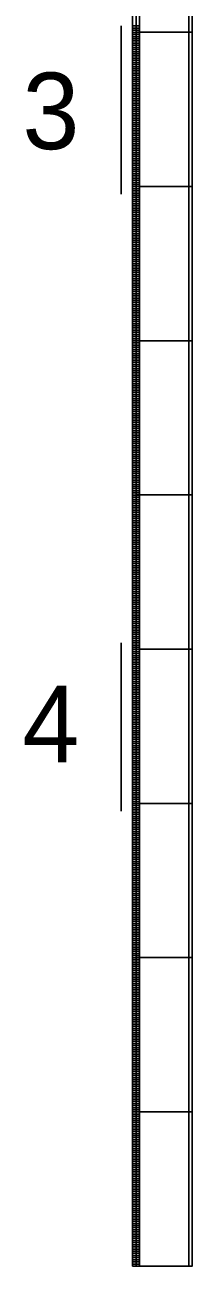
# Model space of a CAD drawing. Extents: x -13 to 29, y -301 to 22.
# Drawn here: x -12.6 to 9.3, y -301.4 to -139.2 of the extents above; entities that cross this region are included whole.
import ezdxf

# ---------------------------------------------------------------- set-up
doc = ezdxf.new("R2010")
doc.units = 0
doc.layers.add('SC_Scratch1', color=7, linetype='Continuous')
doc.layers.add('SH_Text', color=7, linetype='Continuous')

msp = doc.modelspace()

# ---------------------------------------------------------------- linework, layer by layer
at = {"layer": 'SH_Text'}
for p, q in [((1.5, -140.14), (1.5, -119.98)), ((2.4, -140.14), (2.4, -119.98)), ((8.84, -140.14), (8.84, -119.98)), ((0, -139.28), (0, -161.28)), ((1.5, -139.3), (2.4, -139.3)), ((1.5, -139.58), (2.4, -139.58)), ((1.5, -139.86), (2.4, -139.86)), ((1.5, -140.14), (2.4, -140.14)), ((1.5, -140.14), (2.4, -140.14)), ((1.5, -160.3), (1.5, -140.14)), ((1.5, -140.42), (2.4, -140.42)), ((1.5, -140.7), (2.4, -140.7)), ((1.5, -140.98), (2.4, -140.98)), ((2.4, -160.3), (2.4, -140.14)), ((8.84, -160.3), (8.84, -140.14)), ((1.5, -141.26), (2.4, -141.26)), ((1.5, -141.54), (2.4, -141.54)), ((1.5, -141.82), (2.4, -141.82)), ((1.5, -142.1), (2.4, -142.1)), ((1.5, -142.38), (2.4, -142.38)), ((1.5, -142.66), (2.4, -142.66)), ((1.5, -142.94), (2.4, -142.94)), ((1.5, -143.22), (2.4, -143.22)), ((1.5, -143.5), (2.4, -143.5)), ((1.5, -143.78), (2.4, -143.78)), ((1.5, -144.06), (2.4, -144.06)), ((1.5, -144.34), (2.4, -144.34)), ((1.5, -144.62), (2.4, -144.62)), ((1.5, -144.9), (2.4, -144.9)), ((1.5, -145.18), (2.4, -145.18)), ((1.5, -145.46), (2.4, -145.46)), ((1.5, -145.74), (2.4, -145.74)), ((1.5, -146.02), (2.4, -146.02)), ((1.5, -146.3), (2.4, -146.3)), ((1.5, -146.58), (2.4, -146.58)), ((1.5, -146.86), (2.4, -146.86)), ((1.5, -147.14), (2.4, -147.14)), ((1.5, -147.42), (2.4, -147.42)), ((1.5, -147.7), (2.4, -147.7)), ((1.5, -147.98), (2.4, -147.98)), ((1.5, -148.26), (2.4, -148.26)), ((1.5, -148.54), (2.4, -148.54)), ((1.5, -148.82), (2.4, -148.82)), ((1.5, -149.1), (2.4, -149.1)), ((1.5, -149.38), (2.4, -149.38)), ((1.5, -149.66), (2.4, -149.66)), ((1.5, -149.94), (2.4, -149.94)), ((1.5, -150.22), (2.4, -150.22)), ((1.5, -150.5), (2.4, -150.5)), ((1.5, -150.78), (2.4, -150.78)), ((1.5, -151.06), (2.4, -151.06)), ((1.5, -151.34), (2.4, -151.34)), ((1.5, -151.62), (2.4, -151.62)), ((1.5, -151.9), (2.4, -151.9)), ((1.5, -152.18), (2.4, -152.18)), ((1.5, -152.46), (2.4, -152.46)), ((1.5, -152.74), (2.4, -152.74)), ((1.5, -153.02), (2.4, -153.02)), ((1.5, -153.3), (2.4, -153.3)), ((1.5, -153.58), (2.4, -153.58)), ((1.5, -153.86), (2.4, -153.86)), ((1.5, -154.14), (2.4, -154.14)), ((1.5, -154.42), (2.4, -154.42)), ((1.5, -154.7), (2.4, -154.7)), ((1.5, -154.98), (2.4, -154.98)), ((1.5, -155.26), (2.4, -155.26)), ((1.5, -155.54), (2.4, -155.54)), ((1.5, -155.82), (2.4, -155.82)), ((1.5, -156.1), (2.4, -156.1)), ((1.5, -156.38), (2.4, -156.38)), ((1.5, -156.66), (2.4, -156.66)), ((1.5, -156.94), (2.4, -156.94)), ((1.5, -157.22), (2.4, -157.22)), ((1.5, -157.5), (2.4, -157.5)), ((1.5, -157.78), (2.4, -157.78)), ((1.5, -158.06), (2.4, -158.06)), ((1.5, -158.34), (2.4, -158.34)), ((1.5, -158.62), (2.4, -158.62)), ((1.5, -158.9), (2.4, -158.9)), ((1.5, -159.18), (2.4, -159.18)), ((1.5, -159.46), (2.4, -159.46)), ((1.5, -159.74), (2.4, -159.74)), ((1.5, -160.02), (2.4, -160.02)), ((1.5, -160.3), (2.4, -160.3)), ((1.5, -160.3), (2.4, -160.3)), ((1.5, -180.46), (1.5, -160.3)), ((1.5, -160.58), (2.4, -160.58)), ((2.4, -180.46), (2.4, -160.3)), ((8.84, -180.46), (8.84, -160.3)), ((1.5, -160.86), (2.4, -160.86)), ((1.5, -161.14), (2.4, -161.14)), ((1.5, -161.42), (2.4, -161.42)), ((1.5, -161.7), (2.4, -161.7)), ((1.5, -161.98), (2.4, -161.98)), ((1.5, -162.26), (2.4, -162.26)), ((1.5, -162.54), (2.4, -162.54)), ((1.5, -162.82), (2.4, -162.82)), ((1.5, -163.1), (2.4, -163.1)), ((1.5, -163.38), (2.4, -163.38)), ((1.5, -163.66), (2.4, -163.66)), ((1.5, -163.94), (2.4, -163.94)), ((1.5, -164.22), (2.4, -164.22)), ((1.5, -164.5), (2.4, -164.5)), ((1.5, -164.78), (2.4, -164.78)), ((1.5, -165.06), (2.4, -165.06)), ((1.5, -165.34), (2.4, -165.34)), ((1.5, -165.62), (2.4, -165.62)), ((1.5, -165.9), (2.4, -165.9)), ((1.5, -166.18), (2.4, -166.18)), ((1.5, -166.46), (2.4, -166.46)), ((1.5, -166.74), (2.4, -166.74)), ((1.5, -167.02), (2.4, -167.02)), ((1.5, -167.3), (2.4, -167.3)), ((1.5, -167.58), (2.4, -167.58)), ((1.5, -167.86), (2.4, -167.86)), ((1.5, -168.14), (2.4, -168.14)), ((1.5, -168.42), (2.4, -168.42)), ((1.5, -168.7), (2.4, -168.7)), ((1.5, -168.98), (2.4, -168.98)), ((1.5, -169.26), (2.4, -169.26)), ((1.5, -169.54), (2.4, -169.54)), ((1.5, -169.82), (2.4, -169.82)), ((1.5, -170.1), (2.4, -170.1)), ((1.5, -170.38), (2.4, -170.38)), ((1.5, -170.66), (2.4, -170.66)), ((1.5, -170.94), (2.4, -170.94)), ((1.5, -171.22), (2.4, -171.22)), ((1.5, -171.5), (2.4, -171.5)), ((1.5, -171.78), (2.4, -171.78)), ((1.5, -172.06), (2.4, -172.06)), ((1.5, -172.34), (2.4, -172.34)), ((1.5, -172.62), (2.4, -172.62)), ((1.5, -172.9), (2.4, -172.9)), ((1.5, -173.18), (2.4, -173.18)), ((1.5, -173.46), (2.4, -173.46)), ((1.5, -173.74), (2.4, -173.74)), ((1.5, -174.02), (2.4, -174.02)), ((1.5, -174.3), (2.4, -174.3)), ((1.5, -174.58), (2.4, -174.58)), ((1.5, -174.86), (2.4, -174.86)), ((1.5, -175.14), (2.4, -175.14)), ((1.5, -175.42), (2.4, -175.42)), ((1.5, -175.7), (2.4, -175.7)), ((1.5, -175.98), (2.4, -175.98)), ((1.5, -176.26), (2.4, -176.26)), ((1.5, -176.54), (2.4, -176.54)), ((1.5, -176.82), (2.4, -176.82)), ((1.5, -177.1), (2.4, -177.1)), ((1.5, -177.38), (2.4, -177.38)), ((1.5, -177.66), (2.4, -177.66)), ((1.5, -177.94), (2.4, -177.94)), ((1.5, -178.22), (2.4, -178.22)), ((1.5, -178.5), (2.4, -178.5)), ((1.5, -178.78), (2.4, -178.78)), ((1.5, -179.06), (2.4, -179.06)), ((1.5, -179.34), (2.4, -179.34)), ((1.5, -179.62), (2.4, -179.62)), ((1.5, -179.9), (2.4, -179.9)), ((1.5, -180.18), (2.4, -180.18)), ((1.5, -180.46), (2.4, -180.46)), ((1.5, -180.46), (2.4, -180.46)), ((1.5, -200.62), (1.5, -180.46)), ((1.5, -180.74), (2.4, -180.74)), ((1.5, -181.02), (2.4, -181.02)), ((1.5, -181.3), (2.4, -181.3)), ((1.5, -181.58), (2.4, -181.58)), ((2.4, -200.62), (2.4, -180.46)), ((8.84, -200.62), (8.84, -180.46)), ((1.5, -181.86), (2.4, -181.86)), ((1.5, -182.14), (2.4, -182.14)), ((1.5, -182.42), (2.4, -182.42)), ((1.5, -182.7), (2.4, -182.7)), ((1.5, -182.98), (2.4, -182.98)), ((1.5, -183.26), (2.4, -183.26)), ((1.5, -183.54), (2.4, -183.54)), ((1.5, -183.82), (2.4, -183.82)), ((1.5, -184.1), (2.4, -184.1)), ((1.5, -184.38), (2.4, -184.38)), ((1.5, -184.66), (2.4, -184.66)), ((1.5, -184.94), (2.4, -184.94)), ((1.5, -185.22), (2.4, -185.22)), ((1.5, -185.5), (2.4, -185.5)), ((1.5, -185.78), (2.4, -185.78)), ((1.5, -186.06), (2.4, -186.06)), ((1.5, -186.34), (2.4, -186.34)), ((1.5, -186.62), (2.4, -186.62)), ((1.5, -186.9), (2.4, -186.9)), ((1.5, -187.18), (2.4, -187.18)), ((1.5, -187.46), (2.4, -187.46)), ((1.5, -187.74), (2.4, -187.74)), ((1.5, -188.02), (2.4, -188.02)), ((1.5, -188.3), (2.4, -188.3)), ((1.5, -188.58), (2.4, -188.58)), ((1.5, -188.86), (2.4, -188.86)), ((1.5, -189.14), (2.4, -189.14)), ((1.5, -189.42), (2.4, -189.42)), ((1.5, -189.7), (2.4, -189.7)), ((1.5, -189.98), (2.4, -189.98)), ((1.5, -190.26), (2.4, -190.26)), ((1.5, -190.54), (2.4, -190.54)), ((1.5, -190.82), (2.4, -190.82)), ((1.5, -191.1), (2.4, -191.1)), ((1.5, -191.38), (2.4, -191.38)), ((1.5, -191.66), (2.4, -191.66)), ((1.5, -191.94), (2.4, -191.94)), ((1.5, -192.22), (2.4, -192.22)), ((1.5, -192.5), (2.4, -192.5)), ((1.5, -192.78), (2.4, -192.78)), ((1.5, -193.06), (2.4, -193.06)), ((1.5, -193.34), (2.4, -193.34)), ((1.5, -193.62), (2.4, -193.62)), ((1.5, -193.9), (2.4, -193.9)), ((1.5, -194.18), (2.4, -194.18)), ((1.5, -194.46), (2.4, -194.46)), ((1.5, -194.74), (2.4, -194.74)), ((1.5, -195.02), (2.4, -195.02)), ((1.5, -195.3), (2.4, -195.3)), ((1.5, -195.58), (2.4, -195.58)), ((1.5, -195.86), (2.4, -195.86)), ((1.5, -196.14), (2.4, -196.14)), ((1.5, -196.42), (2.4, -196.42)), ((1.5, -196.7), (2.4, -196.7)), ((1.5, -196.98), (2.4, -196.98)), ((1.5, -197.26), (2.4, -197.26)), ((1.5, -197.54), (2.4, -197.54)), ((1.5, -197.82), (2.4, -197.82)), ((1.5, -198.1), (2.4, -198.1)), ((1.5, -198.38), (2.4, -198.38)), ((1.5, -198.66), (2.4, -198.66)), ((1.5, -198.94), (2.4, -198.94)), ((1.5, -199.22), (2.4, -199.22)), ((1.5, -199.5), (2.4, -199.5)), ((1.5, -199.78), (2.4, -199.78)), ((1.5, -200.06), (2.4, -200.06)), ((1.5, -200.34), (2.4, -200.34)), ((1.5, -200.62), (2.4, -200.62)), ((1.5, -200.62), (2.4, -200.62)), ((1.5, -220.78), (1.5, -200.62)), ((1.5, -200.9), (2.4, -200.9)), ((1.5, -201.18), (2.4, -201.18)), ((2.4, -220.78), (2.4, -200.62)), ((8.84, -220.78), (8.84, -200.62)), ((1.5, -201.46), (2.4, -201.46)), ((1.5, -201.74), (2.4, -201.74)), ((1.5, -202.02), (2.4, -202.02)), ((1.5, -202.3), (2.4, -202.3)), ((1.5, -202.58), (2.4, -202.58)), ((1.5, -202.86), (2.4, -202.86)), ((1.5, -203.14), (2.4, -203.14)), ((1.5, -203.42), (2.4, -203.42)), ((1.5, -203.7), (2.4, -203.7)), ((1.5, -203.98), (2.4, -203.98)), ((1.5, -204.26), (2.4, -204.26)), ((1.5, -204.54), (2.4, -204.54)), ((1.5, -204.82), (2.4, -204.82)), ((1.5, -205.1), (2.4, -205.1)), ((1.5, -205.38), (2.4, -205.38)), ((1.5, -205.66), (2.4, -205.66)), ((1.5, -205.94), (2.4, -205.94)), ((1.5, -206.22), (2.4, -206.22)), ((1.5, -206.5), (2.4, -206.5)), ((1.5, -206.78), (2.4, -206.78)), ((1.5, -207.06), (2.4, -207.06)), ((1.5, -207.34), (2.4, -207.34)), ((1.5, -207.62), (2.4, -207.62)), ((1.5, -207.9), (2.4, -207.9)), ((1.5, -208.18), (2.4, -208.18)), ((1.5, -208.46), (2.4, -208.46)), ((1.5, -208.74), (2.4, -208.74)), ((1.5, -209.02), (2.4, -209.02)), ((1.5, -209.3), (2.4, -209.3)), ((1.5, -209.58), (2.4, -209.58)), ((1.5, -209.86), (2.4, -209.86)), ((1.5, -210.14), (2.4, -210.14)), ((1.5, -210.42), (2.4, -210.42)), ((1.5, -210.7), (2.4, -210.7)), ((1.5, -210.98), (2.4, -210.98)), ((1.5, -211.26), (2.4, -211.26)), ((1.5, -211.54), (2.4, -211.54)), ((1.5, -211.82), (2.4, -211.82)), ((1.5, -212.1), (2.4, -212.1)), ((1.5, -212.38), (2.4, -212.38)), ((1.5, -212.66), (2.4, -212.66)), ((1.5, -212.94), (2.4, -212.94)), ((1.5, -213.22), (2.4, -213.22)), ((1.5, -213.5), (2.4, -213.5)), ((1.5, -213.78), (2.4, -213.78)), ((1.5, -214.06), (2.4, -214.06)), ((1.5, -214.34), (2.4, -214.34)), ((1.5, -214.62), (2.4, -214.62)), ((1.5, -214.9), (2.4, -214.9)), ((1.5, -215.18), (2.4, -215.18)), ((1.5, -215.46), (2.4, -215.46)), ((1.5, -215.74), (2.4, -215.74)), ((1.5, -216.02), (2.4, -216.02)), ((1.5, -216.3), (2.4, -216.3)), ((1.5, -216.58), (2.4, -216.58)), ((1.5, -216.86), (2.4, -216.86)), ((1.5, -217.14), (2.4, -217.14)), ((1.5, -217.42), (2.4, -217.42)), ((1.5, -217.7), (2.4, -217.7)), ((1.5, -217.98), (2.4, -217.98)), ((1.5, -218.26), (2.4, -218.26)), ((1.5, -218.54), (2.4, -218.54)), ((1.5, -218.82), (2.4, -218.82)), ((0, -219.92), (0, -241.92)), ((1.5, -219.1), (2.4, -219.1)), ((1.5, -219.38), (2.4, -219.38)), ((1.5, -219.66), (2.4, -219.66)), ((1.5, -219.94), (2.4, -219.94)), ((1.5, -220.22), (2.4, -220.22)), ((1.5, -220.5), (2.4, -220.5)), ((1.5, -220.78), (2.4, -220.78)), ((1.5, -220.78), (2.4, -220.78)), ((1.5, -240.94), (1.5, -220.78)), ((1.5, -221.06), (2.4, -221.06)), ((1.5, -221.34), (2.4, -221.34)), ((1.5, -221.62), (2.4, -221.62)), ((1.5, -221.9), (2.4, -221.9)), ((1.5, -222.18), (2.4, -222.18)), ((2.4, -240.94), (2.4, -220.78)), ((8.84, -240.94), (8.84, -220.78)), ((1.5, -222.46), (2.4, -222.46)), ((1.5, -222.74), (2.4, -222.74)), ((1.5, -223.02), (2.4, -223.02)), ((1.5, -223.3), (2.4, -223.3)), ((1.5, -223.58), (2.4, -223.58)), ((1.5, -223.86), (2.4, -223.86)), ((1.5, -224.14), (2.4, -224.14)), ((1.5, -224.42), (2.4, -224.42)), ((1.5, -224.7), (2.4, -224.7)), ((1.5, -224.98), (2.4, -224.98)), ((1.5, -225.26), (2.4, -225.26)), ((1.5, -225.54), (2.4, -225.54)), ((1.5, -225.82), (2.4, -225.82)), ((1.5, -226.1), (2.4, -226.1)), ((1.5, -226.38), (2.4, -226.38)), ((1.5, -226.66), (2.4, -226.66)), ((1.5, -226.94), (2.4, -226.94)), ((1.5, -227.22), (2.4, -227.22)), ((1.5, -227.5), (2.4, -227.5)), ((1.5, -227.78), (2.4, -227.78)), ((1.5, -228.06), (2.4, -228.06)), ((1.5, -228.34), (2.4, -228.34)), ((1.5, -228.62), (2.4, -228.62)), ((1.5, -228.9), (2.4, -228.9)), ((1.5, -229.18), (2.4, -229.18)), ((1.5, -229.46), (2.4, -229.46)), ((1.5, -229.74), (2.4, -229.74)), ((1.5, -230.02), (2.4, -230.02)), ((1.5, -230.3), (2.4, -230.3)), ((1.5, -230.58), (2.4, -230.58)), ((1.5, -230.86), (2.4, -230.86)), ((1.5, -231.14), (2.4, -231.14)), ((1.5, -231.42), (2.4, -231.42)), ((1.5, -231.7), (2.4, -231.7)), ((1.5, -231.98), (2.4, -231.98)), ((1.5, -232.26), (2.4, -232.26)), ((1.5, -232.54), (2.4, -232.54)), ((1.5, -232.82), (2.4, -232.82)), ((1.5, -233.1), (2.4, -233.1)), ((1.5, -233.38), (2.4, -233.38)), ((1.5, -233.66), (2.4, -233.66)), ((1.5, -233.94), (2.4, -233.94)), ((1.5, -234.22), (2.4, -234.22)), ((1.5, -234.5), (2.4, -234.5)), ((1.5, -234.78), (2.4, -234.78)), ((1.5, -235.06), (2.4, -235.06)), ((1.5, -235.34), (2.4, -235.34)), ((1.5, -235.62), (2.4, -235.62)), ((1.5, -235.9), (2.4, -235.9)), ((1.5, -236.18), (2.4, -236.18)), ((1.5, -236.46), (2.4, -236.46)), ((1.5, -236.74), (2.4, -236.74)), ((1.5, -237.02), (2.4, -237.02)), ((1.5, -237.3), (2.4, -237.3)), ((1.5, -237.58), (2.4, -237.58)), ((1.5, -237.86), (2.4, -237.86)), ((1.5, -238.14), (2.4, -238.14)), ((1.5, -238.42), (2.4, -238.42)), ((1.5, -238.7), (2.4, -238.7)), ((1.5, -238.98), (2.4, -238.98)), ((1.5, -239.26), (2.4, -239.26)), ((1.5, -239.54), (2.4, -239.54)), ((1.5, -239.82), (2.4, -239.82)), ((1.5, -240.1), (2.4, -240.1)), ((1.5, -240.38), (2.4, -240.38)), ((1.5, -240.66), (2.4, -240.66)), ((1.5, -240.94), (2.4, -240.94)), ((1.5, -240.94), (2.4, -240.94)), ((1.5, -261.1), (1.5, -240.94)), ((1.5, -241.22), (2.4, -241.22)), ((1.5, -241.5), (2.4, -241.5)), ((1.5, -241.78), (2.4, -241.78)), ((2.4, -261.1), (2.4, -240.94)), ((8.84, -261.1), (8.84, -240.94)), ((1.5, -242.06), (2.4, -242.06)), ((1.5, -242.34), (2.4, -242.34)), ((1.5, -242.62), (2.4, -242.62)), ((1.5, -242.9), (2.4, -242.9)), ((1.5, -243.18), (2.4, -243.18)), ((1.5, -243.46), (2.4, -243.46)), ((1.5, -243.74), (2.4, -243.74)), ((1.5, -244.02), (2.4, -244.02)), ((1.5, -244.3), (2.4, -244.3)), ((1.5, -244.58), (2.4, -244.58)), ((1.5, -244.86), (2.4, -244.86)), ((1.5, -245.14), (2.4, -245.14)), ((1.5, -245.42), (2.4, -245.42)), ((1.5, -245.7), (2.4, -245.7)), ((1.5, -245.98), (2.4, -245.98)), ((1.5, -246.26), (2.4, -246.26)), ((1.5, -246.54), (2.4, -246.54)), ((1.5, -246.82), (2.4, -246.82)), ((1.5, -247.1), (2.4, -247.1)), ((1.5, -247.38), (2.4, -247.38)), ((1.5, -247.66), (2.4, -247.66)), ((1.5, -247.94), (2.4, -247.94)), ((1.5, -248.22), (2.4, -248.22)), ((1.5, -248.5), (2.4, -248.5)), ((1.5, -248.78), (2.4, -248.78)), ((1.5, -249.06), (2.4, -249.06)), ((1.5, -249.34), (2.4, -249.34)), ((1.5, -249.62), (2.4, -249.62)), ((1.5, -249.9), (2.4, -249.9)), ((1.5, -250.18), (2.4, -250.18)), ((1.5, -250.46), (2.4, -250.46)), ((1.5, -250.74), (2.4, -250.74)), ((1.5, -251.02), (2.4, -251.02)), ((1.5, -251.3), (2.4, -251.3)), ((1.5, -251.58), (2.4, -251.58)), ((1.5, -251.86), (2.4, -251.86)), ((1.5, -252.14), (2.4, -252.14)), ((1.5, -252.42), (2.4, -252.42)), ((1.5, -252.7), (2.4, -252.7)), ((1.5, -252.98), (2.4, -252.98)), ((1.5, -253.26), (2.4, -253.26)), ((1.5, -253.54), (2.4, -253.54)), ((1.5, -253.82), (2.4, -253.82)), ((1.5, -254.1), (2.4, -254.1)), ((1.5, -254.38), (2.4, -254.38)), ((1.5, -254.66), (2.4, -254.66)), ((1.5, -254.94), (2.4, -254.94)), ((1.5, -255.22), (2.4, -255.22)), ((1.5, -255.5), (2.4, -255.5)), ((1.5, -255.78), (2.4, -255.78)), ((1.5, -256.06), (2.4, -256.06)), ((1.5, -256.34), (2.4, -256.34)), ((1.5, -256.62), (2.4, -256.62)), ((1.5, -256.9), (2.4, -256.9)), ((1.5, -257.18), (2.4, -257.18)), ((1.5, -257.46), (2.4, -257.46)), ((1.5, -257.74), (2.4, -257.74)), ((1.5, -258.02), (2.4, -258.02)), ((1.5, -258.3), (2.4, -258.3)), ((1.5, -258.58), (2.4, -258.58)), ((1.5, -258.86), (2.4, -258.86)), ((1.5, -259.14), (2.4, -259.14)), ((1.5, -259.42), (2.4, -259.42)), ((1.5, -259.7), (2.4, -259.7)), ((1.5, -259.98), (2.4, -259.98)), ((1.5, -260.26), (2.4, -260.26)), ((1.5, -260.54), (2.4, -260.54)), ((1.5, -260.82), (2.4, -260.82)), ((1.5, -261.1), (2.4, -261.1)), ((1.5, -261.1), (2.4, -261.1)), ((1.5, -281.26), (1.5, -261.1)), ((2.4, -281.26), (2.4, -261.1)), ((8.84, -281.26), (8.84, -261.1)), ((1.5, -261.38), (2.4, -261.38)), ((1.5, -261.66), (2.4, -261.66)), ((1.5, -261.94), (2.4, -261.94)), ((1.5, -262.22), (2.4, -262.22)), ((1.5, -262.5), (2.4, -262.5)), ((1.5, -262.78), (2.4, -262.78)), ((1.5, -263.06), (2.4, -263.06)), ((1.5, -263.34), (2.4, -263.34)), ((1.5, -263.62), (2.4, -263.62)), ((1.5, -263.9), (2.4, -263.9)), ((1.5, -264.18), (2.4, -264.18)), ((1.5, -264.46), (2.4, -264.46)), ((1.5, -264.74), (2.4, -264.74)), ((1.5, -265.02), (2.4, -265.02)), ((1.5, -265.3), (2.4, -265.3)), ((1.5, -265.58), (2.4, -265.58)), ((1.5, -265.86), (2.4, -265.86)), ((1.5, -266.14), (2.4, -266.14)), ((1.5, -266.42), (2.4, -266.42)), ((1.5, -266.7), (2.4, -266.7)), ((1.5, -266.98), (2.4, -266.98)), ((1.5, -267.26), (2.4, -267.26)), ((1.5, -267.54), (2.4, -267.54)), ((1.5, -267.82), (2.4, -267.82)), ((1.5, -268.1), (2.4, -268.1)), ((1.5, -268.38), (2.4, -268.38)), ((1.5, -268.66), (2.4, -268.66)), ((1.5, -268.94), (2.4, -268.94)), ((1.5, -269.22), (2.4, -269.22)), ((1.5, -269.5), (2.4, -269.5)), ((1.5, -269.78), (2.4, -269.78)), ((1.5, -270.06), (2.4, -270.06)), ((1.5, -270.34), (2.4, -270.34)), ((1.5, -270.62), (2.4, -270.62)), ((1.5, -270.9), (2.4, -270.9)), ((1.5, -271.18), (2.4, -271.18)), ((1.5, -271.46), (2.4, -271.46)), ((1.5, -271.74), (2.4, -271.74)), ((1.5, -272.02), (2.4, -272.02)), ((1.5, -272.3), (2.4, -272.3)), ((1.5, -272.58), (2.4, -272.58)), ((1.5, -272.86), (2.4, -272.86)), ((1.5, -273.14), (2.4, -273.14)), ((1.5, -273.42), (2.4, -273.42)), ((1.5, -273.7), (2.4, -273.7)), ((1.5, -273.98), (2.4, -273.98)), ((1.5, -274.26), (2.4, -274.26)), ((1.5, -274.54), (2.4, -274.54)), ((1.5, -274.82), (2.4, -274.82)), ((1.5, -275.1), (2.4, -275.1)), ((1.5, -275.38), (2.4, -275.38)), ((1.5, -275.66), (2.4, -275.66)), ((1.5, -275.94), (2.4, -275.94)), ((1.5, -276.22), (2.4, -276.22)), ((1.5, -276.5), (2.4, -276.5)), ((1.5, -276.78), (2.4, -276.78)), ((1.5, -277.06), (2.4, -277.06)), ((1.5, -277.34), (2.4, -277.34)), ((1.5, -277.62), (2.4, -277.62)), ((1.5, -277.9), (2.4, -277.9)), ((1.5, -278.18), (2.4, -278.18)), ((1.5, -278.46), (2.4, -278.46)), ((1.5, -278.74), (2.4, -278.74)), ((1.5, -279.02), (2.4, -279.02)), ((1.5, -279.3), (2.4, -279.3)), ((1.5, -279.58), (2.4, -279.58)), ((1.5, -279.86), (2.4, -279.86)), ((1.5, -280.14), (2.4, -280.14)), ((1.5, -280.42), (2.4, -280.42)), ((1.5, -280.7), (2.4, -280.7)), ((1.5, -280.98), (2.4, -280.98)), ((1.5, -281.26), (2.4, -281.26)), ((1.5, -281.26), (2.4, -281.26)), ((1.5, -301.42), (1.5, -281.26)), ((1.5, -281.54), (2.4, -281.54)), ((1.5, -281.82), (2.4, -281.82)), ((1.5, -282.1), (2.4, -282.1)), ((2.4, -301.42), (2.4, -281.26)), ((8.84, -301.42), (8.84, -281.26)), ((1.5, -282.38), (2.4, -282.38)), ((1.5, -282.66), (2.4, -282.66)), ((1.5, -282.94), (2.4, -282.94)), ((1.5, -283.22), (2.4, -283.22)), ((1.5, -283.5), (2.4, -283.5)), ((1.5, -283.78), (2.4, -283.78)), ((1.5, -284.06), (2.4, -284.06)), ((1.5, -284.34), (2.4, -284.34)), ((1.5, -284.62), (2.4, -284.62)), ((1.5, -284.9), (2.4, -284.9)), ((1.5, -285.18), (2.4, -285.18)), ((1.5, -285.46), (2.4, -285.46)), ((1.5, -285.74), (2.4, -285.74)), ((1.5, -286.02), (2.4, -286.02)), ((1.5, -286.3), (2.4, -286.3)), ((1.5, -286.58), (2.4, -286.58)), ((1.5, -286.86), (2.4, -286.86)), ((1.5, -287.14), (2.4, -287.14)), ((1.5, -287.42), (2.4, -287.42)), ((1.5, -287.7), (2.4, -287.7)), ((1.5, -287.98), (2.4, -287.98)), ((1.5, -288.26), (2.4, -288.26)), ((1.5, -288.54), (2.4, -288.54)), ((1.5, -288.82), (2.4, -288.82)), ((1.5, -289.1), (2.4, -289.1)), ((1.5, -289.38), (2.4, -289.38)), ((1.5, -289.66), (2.4, -289.66)), ((1.5, -289.94), (2.4, -289.94)), ((1.5, -290.22), (2.4, -290.22)), ((1.5, -290.5), (2.4, -290.5)), ((1.5, -290.78), (2.4, -290.78)), ((1.5, -291.06), (2.4, -291.06)), ((1.5, -291.34), (2.4, -291.34)), ((1.5, -291.62), (2.4, -291.62)), ((1.5, -291.9), (2.4, -291.9)), ((1.5, -292.18), (2.4, -292.18)), ((1.5, -292.46), (2.4, -292.46)), ((1.5, -292.74), (2.4, -292.74)), ((1.5, -293.02), (2.4, -293.02)), ((1.5, -293.3), (2.4, -293.3)), ((1.5, -293.58), (2.4, -293.58)), ((1.5, -293.86), (2.4, -293.86)), ((1.5, -294.14), (2.4, -294.14)), ((1.5, -294.42), (2.4, -294.42)), ((1.5, -294.7), (2.4, -294.7)), ((1.5, -294.98), (2.4, -294.98)), ((1.5, -295.26), (2.4, -295.26)), ((1.5, -295.54), (2.4, -295.54)), ((1.5, -295.82), (2.4, -295.82)), ((1.5, -296.1), (2.4, -296.1)), ((1.5, -296.38), (2.4, -296.38)), ((1.5, -296.66), (2.4, -296.66)), ((1.5, -296.94), (2.4, -296.94)), ((1.5, -297.22), (2.4, -297.22)), ((1.5, -297.5), (2.4, -297.5)), ((1.5, -297.78), (2.4, -297.78)), ((1.5, -298.06), (2.4, -298.06)), ((1.5, -298.34), (2.4, -298.34)), ((1.5, -298.62), (2.4, -298.62)), ((1.5, -298.9), (2.4, -298.9)), ((1.5, -299.18), (2.4, -299.18)), ((1.5, -299.46), (2.4, -299.46)), ((1.5, -299.74), (2.4, -299.74)), ((1.5, -300.02), (2.4, -300.02)), ((1.5, -300.3), (2.4, -300.3)), ((1.5, -300.58), (2.4, -300.58)), ((1.5, -300.86), (2.4, -300.86)), ((1.5, -301.14), (2.4, -301.14)), ((1.5, -301.42), (2.4, -301.42))]:
    msp.add_line(p, q, dxfattribs=at)
for points in [[(1.95, -119.96), (9.29, -119.96), (9.29, -140.12), (1.95, -140.12)], [(1.95, -140.12), (9.29, -140.12), (9.29, -160.28), (1.95, -160.28)], [(1.95, -160.28), (9.29, -160.28), (9.29, -180.44), (1.95, -180.44)], [(1.95, -180.44), (9.29, -180.44), (9.29, -200.6), (1.95, -200.6)], [(1.95, -200.6), (9.29, -200.6), (9.29, -220.76), (1.95, -220.76)], [(1.95, -220.76), (9.29, -220.76), (9.29, -240.92), (1.95, -240.92)], [(1.95, -240.92), (9.29, -240.92), (9.29, -261.08), (1.95, -261.08)], [(1.95, -261.08), (9.29, -261.08), (9.29, -281.24), (1.95, -281.24)], [(1.95, -281.24), (9.29, -281.24), (9.29, -301.4), (1.95, -301.4)]]:
    msp.add_lwpolyline(points, close=True, dxfattribs=at)

# ---------------------------------------------------------------- texts
at = {"layer": 'SC_Scratch1'}
for s, p in [('3', (-12.89, -155.4)), ('4', (-12.89, -235.55))]:
    msp.add_text(s, height=10, dxfattribs=at).set_placement(p)

doc.saveas('drawing.dxf')
